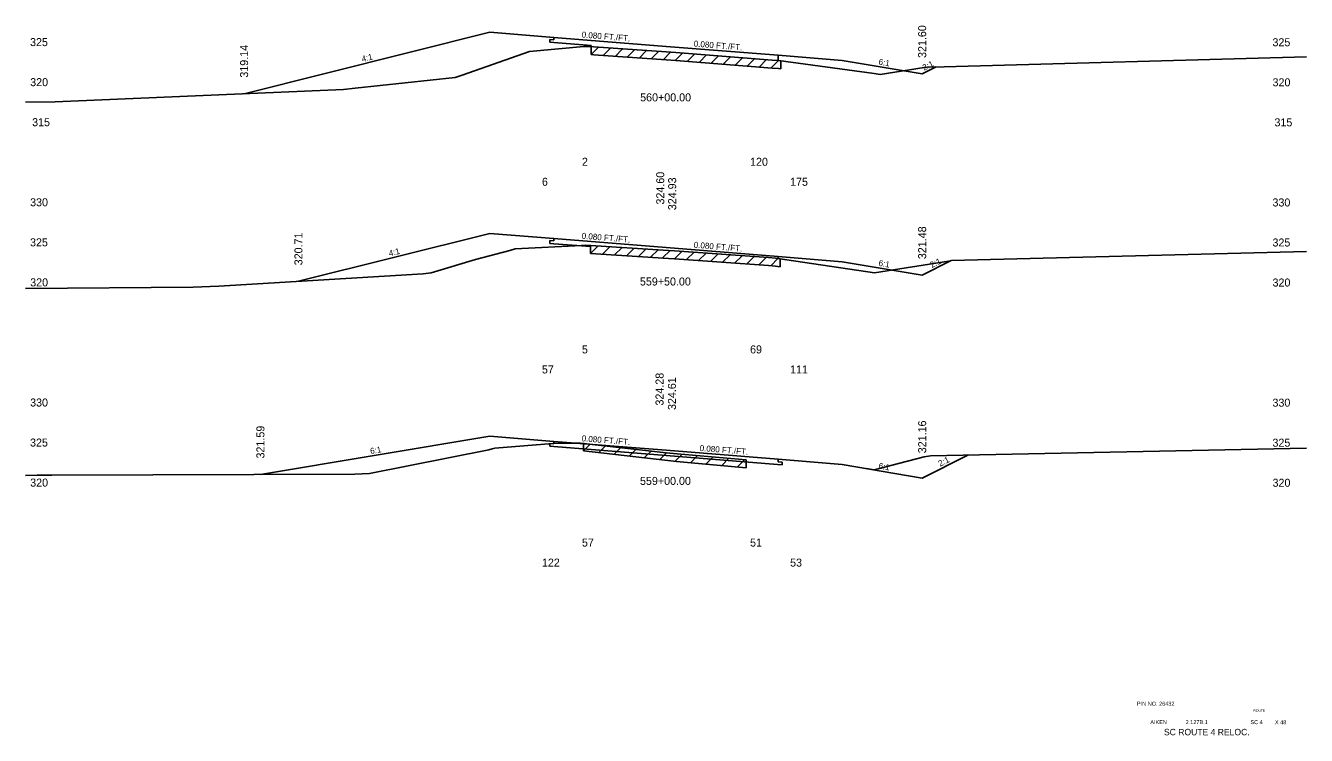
# Model space of a CAD drawing. Extents: x 2967 to 4323, y -3677 to -817.
# Drawn here: x 3555.3 to 3715.3, y -1050.8 to -962.2 of the extents above; entities that cross this region are included whole.
import ezdxf

# ---------------------------------------------------------------- set-up
doc = ezdxf.new("R2010")
doc.units = 0
for name, color, linetype in [('Level 1', 7, 'Continuous'), ('Level 10', 7, 'Continuous'), ('Level 11', 7, 'Continuous'), ('Level 12', 7, 'Continuous'), ('Level 20', 7, 'Continuous'), ('Level 3', 7, 'Continuous'), ('Level 32', 7, 'Continuous'), ('Level 33', 7, 'Continuous'), ('Level 59', 7, 'Continuous'), ('Level 6', 7, 'Continuous'), ('Level 60', 7, 'Continuous'), ('Level 61', 7, 'Continuous'), ('Level 7', 7, 'Continuous')]:
    doc.layers.add(name, color=color, linetype=linetype)

msp = doc.modelspace()

# ---------------------------------------------------------------- linework, layer by layer
at = {"layer": 'Level 1'}
for p, q in [((3625.04, -1015.3), (3625.87, -1014.46)), ((3626.94, -1015.52), (3627.77, -1014.68)), ((3628.84, -1015.74), (3629.67, -1014.9)), ((3630.74, -1015.96), (3631.58, -1015.12)), ((3632.64, -1016.18), (3633.48, -1015.34)), ((3634.55, -1016.4), (3635.39, -1015.56)), ((3636.45, -1016.62), (3637.35, -1015.71)), ((3638.39, -1016.8), (3639.3, -1015.89)), ((3640.33, -1016.97), (3641.25, -1016.06)), ((3642.28, -1017.15), (3643.19, -1016.23)), ((3644.22, -1017.32), (3645.14, -1016.41))]:
    msp.add_line(p, q, dxfattribs=at)
at = {"layer": 'Level 11'}
for p, q in [((3621.35, -963.97), (3620.85, -963.93)), ((3620.85, -963.93), (3620.85, -964.27)), ((3620.85, -964.27), (3621.35, -964.31)), ((3621.35, -963.67), (3621.35, -963.97)), ((3649.35, -965.91), (3649.35, -966.56)), ((3621.35, -988.79), (3621.35, -989.09)), ((3621.35, -989.09), (3620.85, -989.05)), ((3620.85, -989.05), (3620.85, -989.39)), ((3620.85, -989.39), (3621.35, -989.43)), ((3649.35, -991.03), (3649.35, -991.28)), ((3621.35, -1014.41), (3620.85, -1014.37)), ((3620.85, -1014.37), (3620.85, -1014.71)), ((3621.35, -1014.11), (3621.35, -1014.41)), ((3620.85, -1014.71), (3621.35, -1014.75)), ((3649.27, -1016.99), (3649.85, -1017.03)), ((3649.35, -1016.65), (3649.35, -1016.35)), ((3649.85, -1016.69), (3649.35, -1016.65)), ((3649.85, -1017.03), (3649.85, -1016.69))]:
    msp.add_line(p, q, dxfattribs=at)
at = {"layer": 'Level 12'}
for p, q in [((3625.99, -964.68), (3621.35, -964.31)), ((3625.99, -964.82), (3625.99, -964.68)), ((3625.92, -989.79), (3621.35, -989.43)), ((3625.92, -989.65), (3625.92, -989.79)), ((3625.04, -1014.3), (3625.04, -1015.05)), ((3635.35, -1015.87), (3621.35, -1014.75)), ((3649.27, -1016.99), (3635.35, -1015.87))]:
    msp.add_line(p, q, dxfattribs=at)
at = {"layer": 'Level 59'}
for p, q in [((3621.35, -963.67), (3635.35, -964.79)), ((3635.35, -964.79), (3649.35, -965.91)), ((3621.35, -988.79), (3635.35, -989.91)), ((3635.35, -989.91), (3649.35, -991.03)), ((3621.35, -1014.11), (3635.35, -1015.23)), ((3635.35, -1015.23), (3649.35, -1016.35))]:
    msp.add_line(p, q, dxfattribs=at)
at = {"layer": 'Level 6'}
for p, q in [((3613.35, -963.03), (3621.35, -963.67)), ((3649.35, -965.91), (3657.35, -966.57)), ((3613.35, -988.15), (3621.35, -988.79)), ((3649.35, -991.03), (3657.35, -991.69)), ((3613.35, -1013.47), (3621.35, -1014.11)), ((3649.35, -1016.35), (3657.35, -1017.02))]:
    msp.add_line(p, q, dxfattribs=at)
at = {"layer": 'Level 60'}
for p, q in [((3625.08, -964.82), (3625.58, -964.79)), ((3625.58, -964.79), (3626.34, -964.85)), ((3609.87, -968.39), (3618.3, -965.43)), ((3618.3, -965.43), (3625.08, -964.82)), ((3626.34, -964.85), (3635.35, -965.48)), ((3635.35, -965.48), (3636.56, -965.57)), ((3636.56, -965.57), (3648.63, -966.5)), ((3670.09, -967.34), (3715.35, -966.1)), ((3648.63, -966.5), (3649.41, -966.56)), ((3649.41, -966.56), (3661.34, -968.18)), ((3662.12, -968.3), (3667.62, -967.42)), ((3667.62, -967.42), (3667.96, -967.38)), ((3667.96, -967.38), (3670.09, -967.34)), ((3596.51, -970.02), (3609.03, -968.7)), ((3609.03, -968.7), (3609.87, -968.39)), ((3661.34, -968.18), (3662.12, -968.3)), ((3559.06, -971.71), (3595.07, -970.17)), ((3595.07, -970.17), (3596.51, -970.02)), ((3555.35, -971.75), (3559.06, -971.71)), ((3611.57, -991.4), (3615.85, -990.29)), ((3615.85, -990.29), (3616.5, -990.06)), ((3616.5, -990.06), (3624.79, -989.66)), ((3624.79, -989.66), (3625.29, -989.61)), ((3625.29, -989.61), (3635.64, -990.26)), ((3635.64, -990.26), (3636.4, -990.31)), ((3636.4, -990.31), (3648.15, -991.17)), ((3606.03, -993.08), (3611.57, -991.4)), ((3648.15, -991.17), (3649.01, -991.23)), ((3649.01, -991.23), (3660.56, -992.93)), ((3661.41, -993.05), (3670.63, -991.6)), ((3670.63, -991.6), (3671.01, -991.54)), ((3671.01, -991.54), (3674.25, -991.45)), ((3674.25, -991.45), (3715.35, -990.42)), ((3579.48, -994.73), (3605.03, -993.18)), ((3605.03, -993.18), (3606.03, -993.08)), ((3660.56, -992.93), (3661.41, -993.05)), ((3555.35, -995.02), (3576.27, -994.87)), ((3576.27, -994.87), (3579.48, -994.73)), ((3613.97, -1014.96), (3621.22, -1014.36)), ((3621.22, -1014.36), (3621.88, -1014.33)), ((3621.88, -1014.33), (3624.67, -1014.32)), ((3624.67, -1014.32), (3635.35, -1015.56)), ((3598.3, -1018.11), (3613.23, -1015.17)), ((3613.23, -1015.17), (3613.65, -1015.04)), ((3613.65, -1015.04), (3613.97, -1014.96)), ((3625.04, -1015.3), (3636.65, -1016.64)), ((3635.35, -1015.56), (3635.84, -1015.59)), ((3635.84, -1015.59), (3636.73, -1015.66)), ((3636.73, -1015.66), (3645.35, -1016.43)), ((3667.61, -1016.04), (3668.38, -1015.92)), ((3668.38, -1015.92), (3715.35, -1014.96)), ((3636.65, -1016.64), (3645.35, -1017.43)), ((3660.38, -1017.51), (3661.35, -1017.65)), ((3661.35, -1017.65), (3667.61, -1016.04)), ((3555.35, -1018.39), (3556.81, -1018.34)), ((3556.81, -1018.34), (3558.64, -1018.33)), ((3558.64, -1018.33), (3596.46, -1018.22)), ((3596.46, -1018.22), (3598.3, -1018.11))]:
    msp.add_line(p, q, dxfattribs=at)
at = {"layer": 'Level 61'}
for p, q in [((3625.99, -964.82), (3625.99, -965.82)), ((3626.92, -964.89), (3625.99, -965.82)), ((3625.99, -965.82), (3626.34, -965.85)), ((3626.34, -965.85), (3635.35, -966.48)), ((3628.42, -965), (3627.49, -965.93)), ((3629.92, -965.1), (3628.99, -966.04)), ((3631.42, -965.21), (3630.49, -966.14)), ((3632.92, -965.31), (3631.99, -966.25)), ((3634.42, -965.42), (3633.49, -966.35)), ((3635.93, -965.52), (3634.99, -966.46)), ((3637.42, -965.63), (3636.49, -966.56)), ((3638.92, -965.75), (3637.99, -966.68)), ((3640.42, -965.86), (3639.49, -966.79)), ((3641.92, -965.98), (3640.99, -966.91)), ((3643.42, -966.09), (3642.49, -967.02)), ((3644.92, -966.21), (3643.99, -967.14)), ((3646.42, -966.33), (3645.49, -967.25)), ((3635.35, -966.48), (3636.56, -966.57)), ((3636.56, -966.57), (3648.63, -967.5)), ((3647.92, -966.44), (3646.99, -967.37)), ((3649.42, -966.56), (3648.49, -967.49)), ((3648.63, -967.5), (3649.41, -967.56)), ((3649.41, -967.56), (3649.7, -967.6)), ((3649.7, -967.6), (3649.7, -966.6)), ((3625.92, -989.65), (3625.92, -990.65)), ((3626.86, -989.71), (3625.92, -990.65)), ((3628.36, -989.8), (3627.42, -990.75)), ((3629.86, -989.9), (3628.92, -990.84)), ((3631.36, -989.99), (3630.42, -990.93)), ((3632.86, -990.08), (3631.92, -991.03)), ((3634.36, -990.18), (3633.42, -991.12)), ((3635.86, -990.27), (3634.92, -991.21)), ((3637.35, -990.38), (3636.42, -991.31)), ((3625.92, -990.65), (3635.64, -991.26)), ((3635.64, -991.26), (3636.4, -991.31)), ((3636.4, -991.31), (3648.15, -992.17)), ((3638.85, -990.49), (3637.92, -991.42)), ((3640.35, -990.6), (3639.42, -991.53)), ((3641.86, -990.71), (3640.92, -991.64)), ((3643.36, -990.82), (3642.42, -991.75)), ((3644.86, -990.93), (3643.92, -991.86)), ((3646.36, -991.04), (3645.42, -991.97)), ((3647.86, -991.15), (3646.93, -992.08)), ((3649.33, -991.28), (3648.43, -992.19)), ((3649.62, -992.32), (3649.62, -991.32)), ((3648.15, -992.17), (3649.01, -992.23)), ((3649.01, -992.23), (3649.62, -992.32)), ((3625.04, -1014.3), (3625.04, -1015.3)), ((3645.35, -1017.43), (3645.35, -1016.43))]:
    msp.add_line(p, q, dxfattribs=at)
at = {"layer": 'Level 7'}
for p, q in [((3582.64, -970.7), (3613.35, -963.03)), ((3657.35, -966.57), (3667.35, -968.24)), ((3667.35, -968.24), (3669.11, -967.36)), ((3589.43, -994.13), (3613.35, -988.15)), ((3657.35, -991.69), (3667.35, -993.36)), ((3667.35, -993.36), (3670.99, -991.54)), ((3584.68, -1018.25), (3613.35, -1013.47)), ((3667.35, -1018.69), (3673.07, -1015.82)), ((3657.35, -1017.02), (3667.35, -1018.69))]:
    msp.add_line(p, q, dxfattribs=at)

# ---------------------------------------------------------------- texts
at = {"layer": 'Level 1'}
for s, p in [('2', (3624.85, -979.7)), ('120', (3645.85, -979.7)), ('6', (3619.85, -982.2)), ('175', (3650.85, -982.2)), ('5', (3624.85, -1003.13)), ('69', (3645.85, -1003.13)), ('57', (3619.85, -1005.63)), ('111', (3650.85, -1005.63)), ('57', (3624.85, -1027.25)), ('51', (3645.85, -1027.25)), ('122', (3619.85, -1029.75)), ('53', (3650.85, -1029.75))]:
    msp.add_text(s, height=1, dxfattribs=at).set_placement(p)
at = {"layer": 'Level 10'}
for s, p in [('560+00.00', (3632.12, -971.66)), ('559+50.00', (3632.09, -994.65)), ('559+00.00', (3632.1, -1019.55))]:
    msp.add_text(s, height=1, dxfattribs=at).set_placement(p)
for s, p in [('324.60', (3635.13, -984.54)), ('324.28', (3635.04, -1009.64))]:
    msp.add_text(s, height=1, rotation=90, dxfattribs=at).set_placement(p)
at = {"layer": 'Level 20'}
for s, height, p in [('PIN NO. 26432', 0.5, (3694.19, -1047.12)), ('ROUTE', 0.3, (3708.73, -1047.86)), ('AIKEN', 0.5, (3695.85, -1049.42)), (' 2.127B.1', 0.5, (3700.07, -1049.42)), ('SC 4', 0.5, (3708.36, -1049.42)), ('X 48', 0.5, (3711.42, -1049.43)), ('SC ROUTE 4 RELOC.', 0.8, (3697.56, -1050.81))]:
    msp.add_text(s, height=height, dxfattribs=at).set_placement(p)
at = {"layer": 'Level 3'}
for s, p in [(' 325', (3555.53, -964.76)), (' 325', (3710.74, -964.78)), (' 320', (3555.55, -969.76)), (' 320', (3710.75, -969.78)), (' 315', (3555.79, -974.76)), (' 315', (3710.99, -974.78)), (' 330', (3555.54, -984.76)), (' 330', (3710.74, -984.78)), (' 325', (3555.53, -989.76)), (' 325', (3710.74, -989.78)), (' 320', (3555.55, -994.76)), (' 320', (3710.75, -994.78)), (' 330', (3555.54, -1009.76)), (' 330', (3710.74, -1009.78)), (' 325', (3555.53, -1014.76)), (' 325', (3710.74, -1014.78)), (' 320', (3555.55, -1019.76)), (' 320', (3710.75, -1019.78))]:
    msp.add_text(s, height=1, dxfattribs=at).set_placement(p)
at = {"layer": 'Level 32'}
for s, rotation, p in [('0.080 FT./FT.', 355.4261, (3624.79, -963.69)), ('0.080 FT./FT.', 355.4261, (3638.79, -964.81)), ('4:1', 14.0362, (3597.42, -966.75)), ('6:1', 350.5377, (3661.86, -967.07)), ('2:1', 26.5651, (3667.61, -967.83)), ('0.080 FT./FT.', 355.4261, (3624.79, -988.81)), ('4:1', 14.0362, (3600.81, -991.02)), ('0.080 FT./FT.', 355.4261, (3638.79, -989.93)), ('6:1', 350.5377, (3661.86, -992.19)), ('2:1', 26.5651, (3668.55, -992.48)), ('0.080 FT./FT.', 355.4261, (3624.79, -1014.1)), ('6:1', 9.4623, (3598.45, -1015.7)), ('0.080 FT./FT.', 355.4261, (3639.53, -1015.31)), ('6:1', 350.5377, (3661.86, -1017.52)), ('2:1', 26.5651, (3669.59, -1017.28))]:
    msp.add_text(s, height=0.75, rotation=rotation, dxfattribs=at).set_placement(p)
at = {"layer": 'Level 33'}
for s, p in [('321.60', (3667.85, -966.24)), ('319.14', (3583.14, -968.7)), ('320.71', (3589.93, -992.13)), ('321.48', (3667.85, -991.36)), ('321.59', (3585.18, -1016.25)), ('321.16', (3667.85, -1015.6))]:
    msp.add_text(s, height=1, rotation=90, dxfattribs=at).set_placement(p)
at = {"layer": 'Level 59'}
for s, p in [(' 324.93', (3636.62, -985.62)), (' 324.61', (3636.59, -1010.57))]:
    msp.add_text(s, height=1, rotation=90, dxfattribs=at).set_placement(p)

doc.saveas('drawing.dxf')
